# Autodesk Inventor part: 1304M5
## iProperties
Shininess: 80.0
Length Units: 11269
Angle Units: 11279
Time Units: 11290
Mass Units: 11284
Length Display Precision: 3
Angle Display Precision: 2
Compacted: True
Company: Pneumax S.p.A.
Part Number: 1304M5
Material: Default
Description: ANELLO GIREVOLE Ø4 M5
Document SubType Name: Modellazione
Catalog Web Link: www.pneumaxspa.com
Density: 1.59
Volumn: 0.8648857994912436
Area: 17.092995283760587
PropertySet Name: Model Information
Control State: 0
Master: False
Checked Out: False
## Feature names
1. Revolution6
2. Extrusion9
3. Extrusion10
4. Foro6 [Hole]
